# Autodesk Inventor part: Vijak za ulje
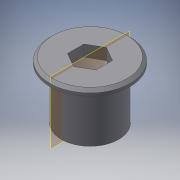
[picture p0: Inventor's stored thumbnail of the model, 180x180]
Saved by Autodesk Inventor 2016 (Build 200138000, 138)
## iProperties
Created: 2015-08
Part Number: Vijak za ulje
Material: Generic
Document SubType Name: Modeling
Designer: stank
Density: 1 g/cm^3
Appearance: Default
Author: stank
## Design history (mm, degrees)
sketch "Sketch1"
  geometry: C1 r 10 at (20, 15) reference; C2 r 10 at (20, 15); 1 further point
  constraints: 1 centre point, 1 coincident
  dimensions: "d1" = 20 diameter of C2
extrude "Extrusion1" new body sketch "Sketch1" distance "d2" = 18; taper "d3" = 0 deg
sketch "Sketch2"
  geometry: C1 r 14 at (0, 0); C2 r 10 at (0, 0) reference; 1 further point
  constraints: 1 centre point, 1 concentric
  dimensions: "d4" = 28 diameter of C1
extrude "Extrusion2" join sketch "Sketch2" distance "d5" = 2; taper "d6" = 0 deg
sketch "Sketch3"
  geometry: L1 (0, 5.774)-(5, 2.887); L2 (5, 2.887)-(5, -2.887); L3 (5, -2.887)-(0, -5.774); L4 (0, -5.774)-(-5, -2.887); L5 (-5, -2.887)-(-5, 2.887); L6 (-5, 2.887)-(0, 5.774); L7 (0, 0)-(0, 14.669); L8 (0, 0)-(16.025, 0); C1 r 14 at (0, 0) reference; 2 further points
  constraints: 16 end point, 1 coincident, 1 horizontal, 1 point on line, 1 vertical, 13 other
  dimensions: "d7" = 10 distance between parallel lines of L5 L2
extrude "Extrusion3" cut sketch "Sketch3" distance "d8" = 4; taper "d9" = 0 deg
workplane "Work Plane1"
sketch "Sketch4"
  geometry: L1 (0, 0)-(0, 5.774) reference; L2 (0, 2.887)-(9.767, 2.887); L3 (8.654, 2.887)-(4, 8.66); L4 (4, 8.66)-(4, 2.887); L5 (4, 0)-(4, 5.774) reference; L6 (4, 2.887)-(8.654, 2.887); 2 further points
  constraints: 8 end point, 2 midpoint, 1 coincident, 1 collinear, 1 horizontal, 1 point on line, 1 vertical
  dimensions: "d10" = 51.125 deg angle of L3 L2
revolve "Revolution1" sketch "Sketch4" stored, may be unused: angle "d11" = 90 deg
chamfer "Chamfer1" distance "d12" = 1; stored, may be unused: second distance "d13" = 2, angle "d14" = 45 deg
body "Solid1"
node "Reference2"
